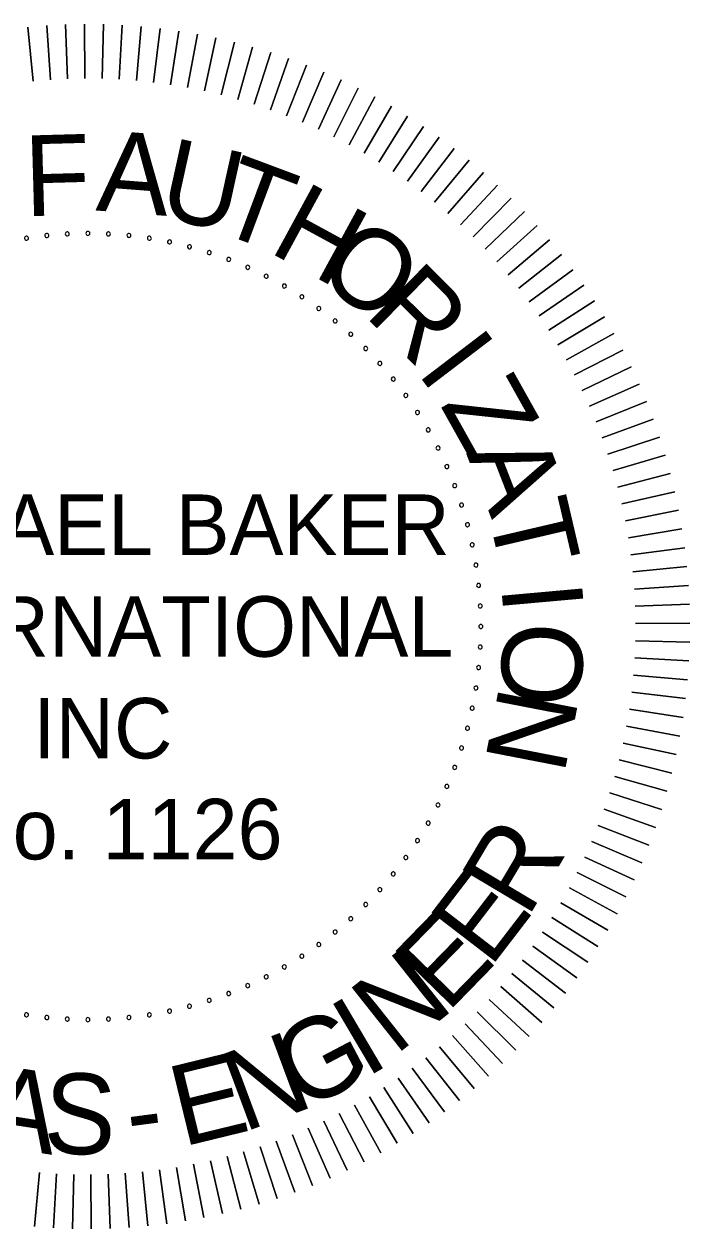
# Model space of a CAD drawing. Extents: x 155 to 3386, y 68 to 2138.
# Drawn here: x 2813.7 to 2951.3, y 322.7 to 571.5 of the extents above; entities that cross this region are included whole.
import ezdxf

# ---------------------------------------------------------------- set-up
doc = ezdxf.new("R2010")
doc.units = 0
doc.layers.add('G-ANNO-TEXT', color=7, linetype='Continuous')

msp = doc.modelspace()

# ---------------------------------------------------------------- linework, layer by layer
at = {"layer": 'G-ANNO-TEXT'}
for points in [[(2815.58, 559.76), (2814.46, 570.93)], [(2814.46, 570.93), (2815.58, 559.76)], [(2819.12, 560.06), (2818.36, 571.26)], [(2818.36, 571.26), (2819.12, 560.06)], [(2822.68, 560.25), (2822.26, 571.46)], [(2822.26, 571.46), (2822.68, 560.25)], [(2826.23, 560.32), (2826.17, 571.55)], [(2826.17, 571.55), (2826.23, 560.32)], [(2829.79, 560.29), (2830.08, 571.51)], [(2830.08, 571.51), (2829.79, 560.29)], [(2833.34, 560.14), (2833.98, 571.34)], [(2833.98, 571.34), (2833.34, 560.14)], [(2836.89, 559.88), (2837.88, 571.06)], [(2837.88, 571.06), (2836.89, 559.88)], [(2840.43, 559.51), (2841.77, 570.65)], [(2841.77, 570.65), (2840.43, 559.51)], [(2843.95, 559.03), (2845.64, 570.12)], [(2845.64, 570.12), (2843.95, 559.03)], [(2847.46, 558.44), (2849.5, 569.47)], [(2849.5, 569.47), (2847.46, 558.44)], [(2850.94, 557.74), (2853.33, 568.7)], [(2853.33, 568.7), (2850.94, 557.74)], [(2854.41, 556.92), (2857.14, 567.81)], [(2857.14, 567.81), (2854.41, 556.92)], [(2857.84, 556), (2860.91, 566.8)], [(2860.91, 566.8), (2857.84, 556)], [(2861.25, 554.98), (2864.66, 565.67)], [(2864.66, 565.67), (2861.25, 554.98)], [(2864.62, 553.84), (2868.36, 564.42)], [(2868.36, 564.42), (2864.62, 553.84)], [(2867.95, 552.61), (2872.03, 563.06)], [(2872.03, 563.06), (2867.95, 552.61)], [(2871.25, 551.26), (2875.65, 561.59)], [(2875.65, 561.59), (2871.25, 551.26)], [(2874.5, 549.82), (2879.22, 560)], [(2879.22, 560), (2874.5, 549.82)], [(2877.7, 548.27), (2882.74, 558.3)], [(2882.74, 558.3), (2877.7, 548.27)], [(2880.85, 546.62), (2886.2, 556.49)], [(2886.2, 556.49), (2880.85, 546.62)], [(2883.95, 544.88), (2889.61, 554.57)], [(2889.61, 554.57), (2883.95, 544.88)], [(2886.99, 543.04), (2892.95, 552.55)], [(2892.95, 552.55), (2886.99, 543.04)], [(2889.98, 541.1), (2896.23, 550.42)], [(2896.23, 550.42), (2889.98, 541.1)], [(2892.9, 539.07), (2899.44, 548.19)], [(2899.44, 548.19), (2892.9, 539.07)], [(2895.76, 536.95), (2902.58, 545.86)], [(2902.58, 545.86), (2895.76, 536.95)], [(2898.54, 534.74), (2905.65, 543.43)], [(2905.65, 543.43), (2898.54, 534.74)], [(2901.26, 532.45), (2908.64, 540.91)], [(2908.64, 540.91), (2901.26, 532.45)], [(2911.54, 538.29), (2903.9, 530.07)], [(2903.9, 530.07), (2911.54, 538.29)], [(2914.36, 535.59), (2906.47, 527.61)], [(2906.47, 527.61), (2914.36, 535.59)], [(2917.1, 532.8), (2908.96, 525.07)], [(2908.96, 525.07), (2917.1, 532.8)], [(2919.75, 529.92), (2911.37, 522.45)], [(2911.37, 522.45), (2919.75, 529.92)], [(2922.3, 526.96), (2913.7, 519.76)], [(2913.7, 519.76), (2922.3, 526.96)], [(2924.76, 523.92), (2915.93, 517)], [(2915.93, 517), (2924.76, 523.92)], [(2927.13, 520.81), (2918.09, 514.16)], [(2918.09, 514.16), (2927.13, 520.81)], [(2929.39, 517.63), (2920.15, 511.27)], [(2920.15, 511.27), (2929.39, 517.63)], [(2931.56, 514.37), (2922.12, 508.3)], [(2922.12, 508.3), (2931.56, 514.37)], [(2933.62, 511.05), (2923.99, 505.28)], [(2923.99, 505.28), (2933.62, 511.05)], [(2935.58, 507.66), (2925.77, 502.2)], [(2925.77, 502.2), (2935.58, 507.66)], [(2937.42, 504.22), (2927.45, 499.07)], [(2927.45, 499.07), (2937.42, 504.22)], [(2939.16, 500.72), (2929.04, 495.88)], [(2929.04, 495.88), (2939.16, 500.72)], [(2940.79, 497.16), (2930.52, 492.65)], [(2930.52, 492.65), (2940.79, 497.16)], [(2942.31, 493.56), (2931.9, 489.37)], [(2931.9, 489.37), (2942.31, 493.56)], [(2943.71, 489.91), (2933.17, 486.05)], [(2933.17, 486.05), (2943.71, 489.91)], [(2945, 486.22), (2934.34, 482.69)], [(2934.34, 482.69), (2945, 486.22)], [(2946.17, 482.49), (2935.41, 479.3)], [(2935.41, 479.3), (2946.17, 482.49)], [(2947.22, 478.73), (2936.37, 475.87)], [(2936.37, 475.87), (2947.22, 478.73)], [(2948.15, 474.93), (2937.22, 472.42)], [(2937.22, 472.42), (2948.15, 474.93)], [(2948.97, 471.11), (2937.96, 468.94)], [(2937.96, 468.94), (2948.97, 471.11)], [(2949.66, 467.26), (2938.59, 465.44)], [(2938.59, 465.44), (2949.66, 467.26)], [(2950.23, 463.39), (2939.11, 461.92)], [(2939.11, 461.92), (2950.23, 463.39)], [(2950.68, 459.51), (2939.52, 458.39)], [(2939.52, 458.39), (2950.68, 459.51)], [(2951.01, 455.61), (2939.82, 454.85)], [(2939.82, 454.85), (2951.01, 455.61)], [(2951.22, 451.71), (2940, 451.29)], [(2940, 451.29), (2951.22, 451.71)], [(2951.3, 447.8), (2940.08, 447.74)], [(2940.08, 447.74), (2951.3, 447.8)], [(2951.26, 443.89), (2940.04, 444.18)], [(2940.04, 444.18), (2951.26, 443.89)], [(2951.1, 439.99), (2939.9, 440.63)], [(2939.9, 440.63), (2951.1, 439.99)], [(2950.81, 436.09), (2939.64, 437.08)], [(2939.64, 437.08), (2950.81, 436.09)], [(2950.41, 432.2), (2939.27, 433.54)], [(2939.27, 433.54), (2950.41, 432.2)], [(2949.88, 428.33), (2938.78, 430.02)], [(2938.78, 430.02), (2949.88, 428.33)], [(2949.23, 424.47), (2938.19, 426.51)], [(2938.19, 426.51), (2949.23, 424.47)], [(2948.46, 420.64), (2937.49, 423.03)], [(2937.49, 423.03), (2948.46, 420.64)], [(2947.56, 416.83), (2936.68, 419.56)], [(2936.68, 419.56), (2947.56, 416.83)], [(2946.55, 413.06), (2935.76, 416.13)], [(2935.76, 416.13), (2946.55, 413.06)], [(2945.43, 409.31), (2934.73, 412.72)], [(2934.73, 412.72), (2945.43, 409.31)], [(2944.18, 405.61), (2933.6, 409.35)], [(2933.6, 409.35), (2944.18, 405.61)], [(2942.82, 401.94), (2932.36, 406.02)], [(2932.36, 406.02), (2942.82, 401.94)], [(2941.34, 398.32), (2931.02, 402.72)], [(2931.02, 402.72), (2941.34, 398.32)], [(2939.75, 394.75), (2929.57, 399.47)], [(2929.57, 399.47), (2939.75, 394.75)], [(2938.05, 391.23), (2928.03, 396.27)], [(2928.03, 396.27), (2938.05, 391.23)], [(2936.24, 387.77), (2926.38, 393.12)], [(2926.38, 393.12), (2936.24, 387.77)], [(2934.33, 384.36), (2924.63, 390.02)], [(2924.63, 390.02), (2934.33, 384.36)], [(2932.3, 381.01), (2922.79, 386.98)], [(2922.79, 386.98), (2932.3, 381.01)], [(2930.17, 377.74), (2920.86, 383.99)], [(2920.86, 383.99), (2930.17, 377.74)], [(2927.94, 374.52), (2918.83, 381.07)], [(2918.83, 381.07), (2927.94, 374.52)], [(2925.61, 371.39), (2916.71, 378.21)], [(2916.71, 378.21), (2925.61, 371.39)], [(2923.19, 368.32), (2914.5, 375.43)], [(2914.5, 375.43), (2923.19, 368.32)], [(2920.66, 365.33), (2912.2, 372.71)], [(2912.2, 372.71), (2920.66, 365.33)], [(2918.05, 362.43), (2909.83, 370.06)], [(2909.83, 370.06), (2918.05, 362.43)], [(2915.34, 359.61), (2907.36, 367.5)], [(2907.36, 367.5), (2915.34, 359.61)], [(2912.55, 356.87), (2904.82, 365.01)], [(2904.82, 365.01), (2912.55, 356.87)], [(2909.68, 354.22), (2902.21, 362.6)], [(2902.21, 362.6), (2909.68, 354.22)], [(2906.72, 351.67), (2899.52, 360.27)], [(2899.52, 360.27), (2906.72, 351.67)], [(2903.68, 349.21), (2896.75, 358.04)], [(2896.75, 358.04), (2903.68, 349.21)], [(2897.38, 344.58), (2891.02, 353.82)], [(2891.02, 353.82), (2897.38, 344.58)], [(2900.57, 346.84), (2893.92, 355.88)], [(2893.92, 355.88), (2900.57, 346.84)], [(2894.13, 342.41), (2888.06, 351.85)], [(2888.06, 351.85), (2894.13, 342.41)], [(2890.8, 340.35), (2885.04, 349.98)], [(2885.04, 349.98), (2890.8, 340.35)], [(2883.97, 336.55), (2878.82, 346.52)], [(2878.82, 346.52), (2883.97, 336.55)], [(2887.42, 338.39), (2881.96, 348.2)], [(2881.96, 348.2), (2887.42, 338.39)], [(2880.47, 334.81), (2875.64, 344.93)], [(2875.64, 344.93), (2880.47, 334.81)], [(2873.32, 331.66), (2869.13, 342.07)], [(2869.13, 342.07), (2873.32, 331.66)], [(2876.92, 333.18), (2872.41, 343.45)], [(2872.41, 343.45), (2876.92, 333.18)], [(2862.25, 327.8), (2859.05, 338.56)], [(2859.05, 338.56), (2862.25, 327.8)], [(2865.98, 328.97), (2862.45, 339.63)], [(2862.45, 339.63), (2865.98, 328.97)], [(2869.67, 330.26), (2865.81, 340.8)], [(2865.81, 340.8), (2869.67, 330.26)], [(2850.86, 325), (2848.7, 336.01)], [(2848.7, 336.01), (2850.86, 325)], [(2854.68, 325.82), (2852.18, 336.75)], [(2852.18, 336.75), (2854.68, 325.82)], [(2858.48, 326.75), (2855.63, 337.6)], [(2855.63, 337.6), (2858.48, 326.75)], [(2815.84, 323.15), (2816.84, 334.33)], [(2816.84, 334.33), (2815.84, 323.15)], [(2819.74, 322.87), (2820.38, 334.07)], [(2820.38, 334.07), (2819.74, 322.87)], [(2823.65, 322.71), (2823.94, 333.93)], [(2823.94, 333.93), (2823.65, 322.71)], [(2827.56, 322.67), (2827.49, 333.89)], [(2827.49, 333.89), (2827.56, 322.67)], [(2831.46, 322.75), (2831.05, 333.97)], [(2831.05, 333.97), (2831.46, 322.75)], [(2835.37, 322.96), (2834.6, 334.15)], [(2834.6, 334.15), (2835.37, 322.96)], [(2839.26, 323.29), (2838.15, 334.45)], [(2838.15, 334.45), (2839.26, 323.29)], [(2843.15, 323.74), (2841.68, 334.86)], [(2841.68, 334.86), (2843.15, 323.74)], [(2847.01, 324.31), (2845.2, 335.38)], [(2845.2, 335.38), (2847.01, 324.31)]]:
    msp.add_lwpolyline(points, dxfattribs=at)
for centre, start, end in [((2814.16, 527.32), 9, 189), ((2818.37, 527.88), 6, 186), ((2818.37, 527.88), 186, 6), ((2822.61, 528.21), 3, 183), ((2822.61, 528.21), 183, 3), ((2826.86, 528.32), 0, 180), ((2826.86, 528.32), 180, 0), ((2831.11, 528.21), 357, 177), ((2831.11, 528.21), 177, 357), ((2835.35, 527.88), 174, 354), ((2835.35, 527.88), 354, 174), ((2839.57, 527.32), 351, 171), ((2814.16, 527.32), 189, 9), ((2839.57, 527.32), 171, 351), ((2843.75, 526.55), 168, 348), ((2843.75, 526.55), 348, 168), ((2847.88, 525.55), 165, 345), ((2847.88, 525.55), 345, 165), ((2851.96, 524.35), 162, 342), ((2851.96, 524.35), 342, 162), ((2855.97, 522.93), 159, 339), ((2855.97, 522.93), 339, 159), ((2859.9, 521.3), 156, 336), ((2859.9, 521.3), 336, 156), ((2863.73, 519.47), 153, 333), ((2863.73, 519.47), 333, 153), ((2867.47, 517.44), 330, 150), ((2867.47, 517.44), 150, 330), ((2871.1, 515.22), 147, 327), ((2871.1, 515.22), 327, 147), ((2874.6, 512.81), 144, 324), ((2874.6, 512.81), 324, 144), ((2877.97, 510.22), 141, 321), ((2877.97, 510.22), 321, 141), ((2881.21, 507.46), 138, 318), ((2881.21, 507.46), 318, 138), ((2884.29, 504.53), 135, 315), ((2884.29, 504.53), 315, 135), ((2887.22, 501.45), 132, 312), ((2887.22, 501.45), 312, 132), ((2889.98, 498.22), 129, 309), ((2889.98, 498.22), 309, 129), ((2892.57, 494.84), 126, 306), ((2892.57, 494.84), 306, 126), ((2894.97, 491.34), 123, 303), ((2894.97, 491.34), 303, 123), ((2897.2, 487.71), 120, 300), ((2897.2, 487.71), 300, 120), ((2899.23, 483.98), 117, 297), ((2899.23, 483.98), 297, 117), ((2901.06, 480.14), 114, 294), ((2901.06, 480.14), 294, 114), ((2902.68, 476.21), 111, 291), ((2902.68, 476.21), 291, 111), ((2904.1, 472.2), 108, 288), ((2904.1, 472.2), 288, 108), ((2905.31, 468.13), 105, 285), ((2905.31, 468.13), 285, 105), ((2906.3, 463.99), 102, 282), ((2906.3, 463.99), 282, 102), ((2907.08, 459.81), 99, 279), ((2907.08, 459.81), 279, 99), ((2907.63, 455.6), 96, 276), ((2907.63, 455.6), 276, 96), ((2907.97, 451.36), 93, 273), ((2907.97, 451.36), 273, 93), ((2908.08, 447.11), 90, 270), ((2908.08, 447.11), 270, 90), ((2907.97, 442.86), 87, 267), ((2907.97, 442.86), 267, 87), ((2907.63, 438.62), 84, 264), ((2907.63, 438.62), 264, 84), ((2907.08, 434.4), 81, 261), ((2907.08, 434.4), 261, 81), ((2906.3, 430.22), 78, 258), ((2906.3, 430.22), 258, 78), ((2905.31, 426.09), 75, 255), ((2905.31, 426.09), 255, 75), ((2904.1, 422.01), 72, 252), ((2904.1, 422.01), 252, 72), ((2902.68, 418), 69, 249), ((2902.68, 418), 249, 69), ((2901.06, 414.07), 66, 246), ((2901.06, 414.07), 246, 66), ((2899.23, 410.24), 63, 243), ((2899.23, 410.24), 243, 63), ((2897.2, 406.5), 60, 240), ((2897.2, 406.5), 240, 60), ((2894.97, 402.87), 57, 237), ((2894.97, 402.87), 237, 57), ((2892.57, 399.37), 54, 234), ((2892.57, 399.37), 234, 54), ((2889.98, 396), 51, 231), ((2889.98, 396), 231, 51), ((2887.22, 392.76), 48, 228), ((2887.22, 392.76), 228, 48), ((2884.29, 389.68), 45, 225), ((2884.29, 389.68), 225, 45), ((2881.21, 386.75), 42, 222), ((2881.21, 386.75), 222, 42), ((2877.97, 383.99), 39, 219), ((2877.97, 383.99), 219, 39), ((2874.6, 381.4), 36, 216), ((2874.6, 381.4), 216, 36), ((2871.1, 378.99), 33, 213), ((2871.1, 378.99), 213, 33), ((2867.47, 376.77), 30, 210), ((2867.47, 376.77), 210, 30), ((2859.9, 372.91), 24, 204), ((2863.73, 374.74), 27, 207), ((2863.73, 374.74), 207, 27), ((2855.97, 371.29), 21, 201), ((2855.97, 371.29), 201, 21), ((2859.9, 372.91), 204, 24), ((2847.88, 368.66), 15, 195), ((2847.88, 368.66), 195, 15), ((2851.96, 369.87), 18, 198), ((2851.96, 369.87), 198, 18), ((2814.16, 366.89), 171, 351), ((2814.16, 366.89), 351, 171), ((2818.37, 366.34), 354, 174), ((2818.37, 366.34), 174, 354), ((2822.61, 366), 357, 177), ((2822.61, 366), 177, 357), ((2826.86, 365.89), 0, 180), ((2826.86, 365.89), 180, 0), ((2831.11, 366), 3, 183), ((2831.11, 366), 183, 3), ((2835.35, 366.34), 6, 186), ((2835.35, 366.34), 186, 6), ((2839.57, 366.89), 9, 189), ((2839.57, 366.89), 189, 9), ((2843.75, 367.67), 12, 192), ((2843.75, 367.67), 192, 12)]:
    msp.add_arc(centre, 0.417, start, end, dxfattribs=at)

# ---------------------------------------------------------------- texts
for s, rotation, p in [('F', 1.5867, (2813.93, 531.84)), ('A', 355.5955, (2828.38, 533.06)), ('U', 347.5481, (2840.99, 531.87)), ('T', 339.5007, (2852.63, 529.09)), ('H', 331.4533, (2863.93, 524.64)), ('O', 323.4059, (2873.5, 519.37)), ('R', 315.3585, (2883.83, 511.46)), ('I', 307.3112, (2894.66, 499.72)), ('Z', 299.2638, (2899.56, 492.93)), ('A', 291.2164, (2905.02, 482.91)), ('T', 283.169, (2909.38, 471.12)), ('I', 275.1216, (2912.27, 455.52)), ('O', 267.0743, (2912.86, 448.35)), ('N', 259.0269, (2911.98, 435.25)), ('R', 59.2262, (2917.73, 386.67)), ('E', 52.4765, (2910, 376.41)), ('E', 45.7268, (2901.11, 367.13)), ('N', 38.4196, (2890.33, 358.33)), ('I', 30.5495, (2884.28, 353.74)), ('G', 27.7404, (2871.1, 346.74)), ('N', 20.4332, (2858.97, 342.54)), ('E', 13.6835, (2846.41, 339.6)), ('A', 351.1991, (2804.81, 340.23)), ('S', 357.9489, (2817.53, 338.38)), ('-', 7.5077, (2835.71, 338.34))]:
    msp.add_text(s, height=16.67, rotation=rotation, dxfattribs=at).set_placement(p)
for s, height, p in [('MICHAEL BAKER', 12.5016, (2766.03, 461.88)), (' INTERNATIONAL', 12.5016, (2764.02, 440.86)), ('INC', 12.502, (2815.54, 419.84)), (' No. 1126', 12.502, (2794.6, 399))]:
    msp.add_text(s, height=height, dxfattribs=at).set_placement(p)

doc.saveas('drawing.dxf')
